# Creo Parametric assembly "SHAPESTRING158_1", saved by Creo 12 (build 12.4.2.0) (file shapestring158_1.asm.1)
Units: Custom; MM, KILOGRAM, SECS

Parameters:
  PTC_WM_ITERATION = "0"
  PTC_WM_VERSION = "-.0"
  PTC_WM_LIFECYCLE_STATE = "In Work"
  PTC_WM_LIFECYCLE = "MO_CADDocument"
  PTC_WM_CREATED_BY = "Maximilian Roepper (Z0017RMS: MO)"
  PTC_WM_CREATED_ON = "18-Sep-26 11:36:42 AM"
  PTC_WM_MODIFIED_BY = "Maximilian Roepper (Z0017RMS: MO)"
  PTC_WM_MODIFIED_ON = "18-Sep-26 11:36:46 AM"
  PDMLINKNUMBER = "PDM000071454953"
  PTC_WM_NAME = "shapestring158_1.asm"
  PTC_WM_NUMBER = "PDM000071454953"

Other parameters: WEIGHT, WEIGHT_FACTOR, WEIGHT_ADD, MC_ERRORS, SUPPLIER, ISPOSITIONINGASSEMBLY

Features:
  1. coordinate system
  2. imported feature
  3. component "SHAPESTRING077_1"
  4. component "SHAPESTRING157_1"

Other named items: DRW_VIEW_ORG, ROUGH-GROB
